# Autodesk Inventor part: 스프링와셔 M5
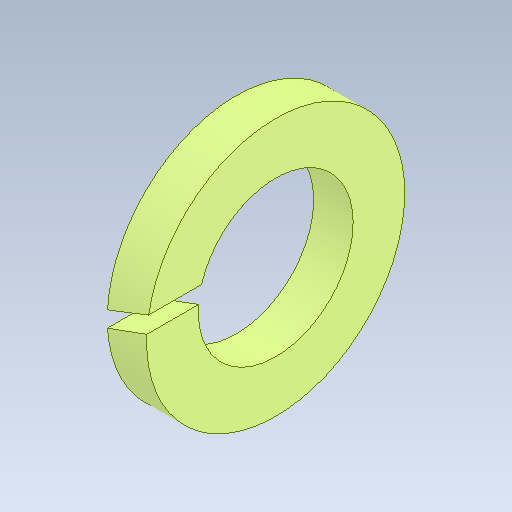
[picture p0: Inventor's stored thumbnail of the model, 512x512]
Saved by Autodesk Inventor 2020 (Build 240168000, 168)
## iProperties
Created: 2024-09
Part Number: 스프링와셔 M5
Material: 강철, 연강
Description: 스프링 잠금 와셔
Document SubType Name: Modeling
Designer: oem
Density: 7.85 g/cm^3
Appearance: 기본값
Author: jhkim
Sending System: Autodesk Inventor 2025
Preprocessor: ST-DEVELOPER v20
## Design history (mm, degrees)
feature "Solid1"
node "솔리드1"
